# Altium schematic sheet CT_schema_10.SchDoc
size 146 x 119 mm
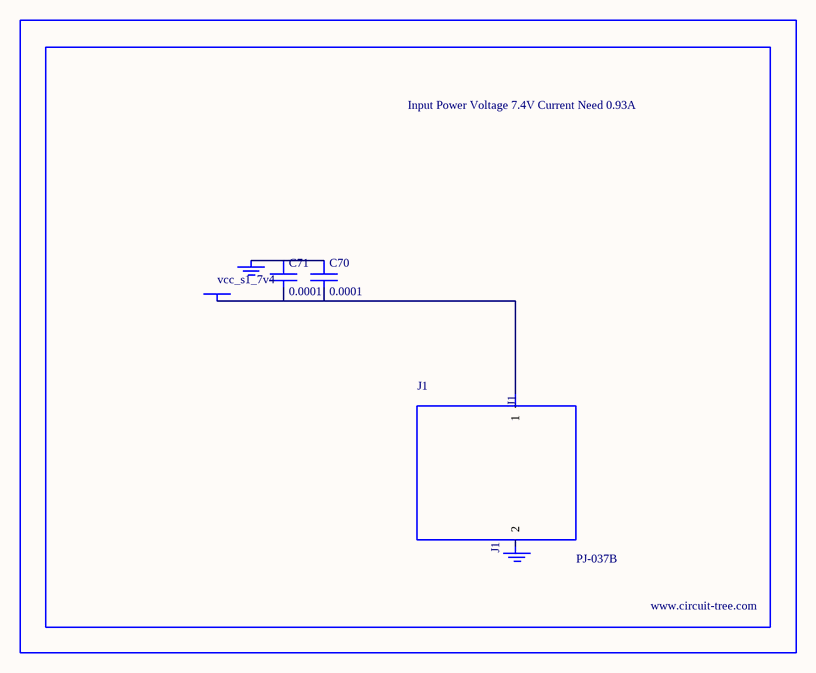
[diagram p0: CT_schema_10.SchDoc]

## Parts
BORDER9  (no value)
C70  0.0001  [EXV-9H]
C71  0.0001  [EXV-9H]
GND_INSTANCE_9_0  (no value)
GND_INSTANCE_9_1  (no value)
J1  PJ-037B  [PJ-037B_PACKAGE]
POWER_INSTANCE_9_0  vcc_s1_7v4

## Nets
NetC70_1: C70.1 C71.1 GND_INSTANCE_9_0.0(GND)
NetC70_2: C70.2 C71.2 J1.1 POWER_INSTANCE_9_0.0(PWR)

Not connected (* = marked no-connect by the designer): GND_INSTANCE_9_1 0(GND); J1 2

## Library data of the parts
BORDER9 = BORDER_PAGE9
C70 C71 = EDK107M035A9HAA
GND_INSTANCE_9_0 GND_INSTANCE_9_1 = GND
POWER_INSTANCE_9_0 = PWR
